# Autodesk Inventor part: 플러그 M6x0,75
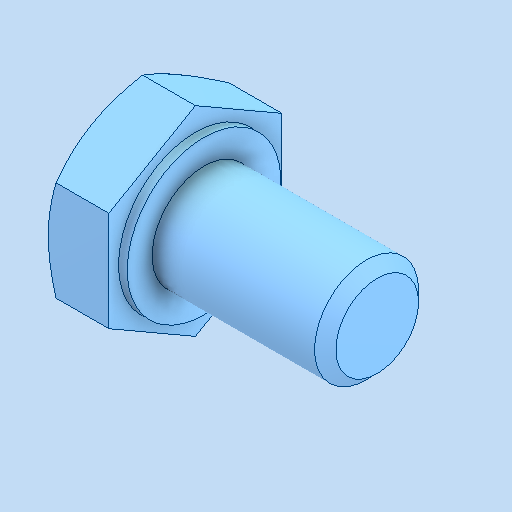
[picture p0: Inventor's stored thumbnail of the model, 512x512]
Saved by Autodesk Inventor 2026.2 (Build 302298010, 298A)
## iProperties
Created: 2026-03
Part Number: 플러그 M6x0,75
Material: 강철, 연강
Description: 6각 머리 볼트 및 6각 머리 나사
Document SubType Name: Modeling
Designer: PC-2-03
Density: 7.85 g/cm^3
Appearance: 기본값
Author: jhkim
Sending System: Autodesk Inventor 2026
Preprocessor: ST-DEVELOPER v20.1
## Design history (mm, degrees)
feature "Solid1"
node "솔리드1"
